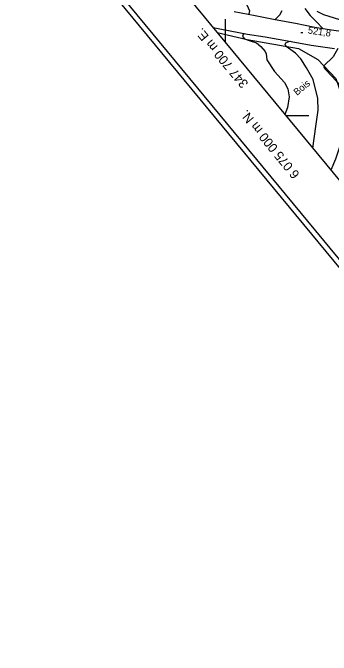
# Model space of a CAD drawing. Extents: x 347059 to 352153, y 6073752 to 6078601.
# Drawn here: x 347561.7 to 347769, y 6074648.1 to 6075066.9 of the extents above; entities that cross this region are included whole.
import ezdxf

# ---------------------------------------------------------------- set-up
doc = ezdxf.new("R2010")
doc.units = 0
for name, color, linetype in [('Level 1', 7, 'Continuous'), ('Level 19', 7, 'Continuous'), ('Level 2', 7, 'Continuous'), ('Level 21', 7, 'Continuous'), ('Level 3', 7, 'Continuous'), ('Level 44', 7, 'Continuous'), ('Level 60', 7, 'Continuous'), ('Level 61', 7, 'Continuous')]:
    doc.layers.add(name, color=color, linetype=linetype)

msp = doc.modelspace()

# ---------------------------------------------------------------- linework, layer by layer
at = {"layer": 'Level 1'}
msp.add_lwpolyline([(347773.33, 6075043.59), (347770.36, 6075038.18), (347764.36, 6075032.34), (347764.3, 6075031.5), (347765.2, 6075030.13), (347770, 6075025.24), (347773.43, 6075021.34), (347774.76, 6075019.13), (347775.23, 6075017), (347776.99, 6075008.78), (347777.41, 6075001.82), (347777.76, 6074999.99), (347778.25, 6074993.54), (347779.06, 6074993.15)], dxfattribs=at)
at = {"layer": 'Level 19'}
for points in [[(347732.67, 6075062.66), (347735.71, 6075065.67), (347737.22, 6075068.49)], [(347751.92, 6075069.68), (347755.45, 6075065.18), (347759.56, 6075061.15), (347763.54, 6075056.73)]]:
    msp.add_lwpolyline(points, dxfattribs=at)
at = {"layer": 'Level 2'}
for points in [[(347693.09, 6075107.08), (347696.94, 6075103.34), (347702.44, 6075093.04), (347704.43, 6075086.79), (347706.07, 6075083.88), (347708.88, 6075077.1), (347712.23, 6075074.08), (347714.07, 6075072.05), (347715.8, 6075068.14), (347715.35, 6075065.99)], [(347712.19, 6075053.53), (347711.63, 6075052.79), (347711.3, 6075051.45), (347712.63, 6075050.05), (347715.71, 6075048.92), (347720.4, 6075047.29), (347723.31, 6075044.95), (347726.06, 6075041.69), (347726.8, 6075040.19), (347727.11, 6075036.21)], [(347757.15, 6074978.58), (347759.13, 6074992.7), (347760.47, 6075003.39), (347760.32, 6075010.96), (347757.26, 6075023.39), (347753.07, 6075031.02), (347749.24, 6075036.97), (347745.8, 6075040.72), (347739.66, 6075045), (347739.14, 6075046.55), (347739.5, 6075047.39), (347740.68, 6075047.72)], [(347742.5, 6075048.39), (347742.31, 6075048.15), (347740.68, 6075047.72)], [(347727.11, 6075036.21), (347732.09, 6075028.59), (347738.57, 6075021.56), (347740.81, 6075017.34), (347741.67, 6075012.23), (347740.64, 6075005.28), (347738.95, 6075000.61)]]:
    msp.add_lwpolyline(points, dxfattribs=at)
at = {"layer": 'Level 21'}
for points in [[(347705.83, 6075067.75), (347719.45, 6075065.23), (347732.67, 6075062.66), (347745.79, 6075060.13), (347758.5, 6075057.48), (347763.54, 6075056.73), (347770.69, 6075055.65), (347782.01, 6075054.06), (347794.01, 6075052.37), (347806.38, 6075050.08), (347821.95, 6075047.53), (347837.03, 6075045.32), (347852.37, 6075043.16), (347871.71, 6075040.15), (347874.49, 6075042.05), (347876.01, 6075044), (347876.24, 6075047.77), (347876.48, 6075053.82), (347874.97, 6075059.22), (347871.12, 6075070.29)], [(347692.07, 6075057.34), (347697.53, 6075056.18), (347714.51, 6075053.11), (347726.02, 6075051.26), (347742.92, 6075048.32), (347756.03, 6075045.91), (347771.32, 6075043.76)]]:
    msp.add_lwpolyline(points, dxfattribs=at)
at = {"layer": 'Level 3'}
msp.add_line((347749.37, 6075054.19), (347750.56, 6075054.01), dxfattribs=at)
at = {"layer": 'Level 44'}
for points in [[(347861.15, 6075079.91), (347865.37, 6075057.26), (347869.96, 6075052.12), (347876.09, 6075046.92), (347875.58, 6075044.84), (347872.78, 6075041.91), (347817.9, 6075050.53), (347785.78, 6075058.96), (347764.27, 6075065.62), (347759.87, 6075067.81)], [(347694.84, 6075054), (347714.37, 6075049.54), (347747.86, 6075043.77), (347760.26, 6075036.39), (347771.98, 6075024.12), (347777.92, 6075007.16), (347780.53, 6074997.41), (347771.93, 6074971.61), (347768.87, 6074964.4)]]:
    msp.add_lwpolyline(points, dxfattribs=at)
at = {"layer": 'Level 60'}
for p, q in [((347700, 6075062.75), (347700, 6075047.75)), ((347739.47, 6075000), (347754.54, 6075000))]:
    msp.add_line(p, q, dxfattribs=at)
msp.add_lwpolyline([(347109.95, 6075761.81), (348728.53, 6073803.05), (351407.22, 6076016.53), (349788.63, 6077975.29)], close=True, dxfattribs=at)
for points in [[(347058.77, 6075766.69), (348723.67, 6073751.88)], [(347063.49, 6075766.23), (348724.12, 6073756.59)]]:
    msp.add_lwpolyline(points, dxfattribs=at)

# ---------------------------------------------------------------- texts
at = {"layer": 'Level 3'}
msp.add_text('521,8', height=4.5, rotation=351.7601, dxfattribs=at).set_placement((347753.64, 6075053.52))
at = {"layer": 'Level 44'}
msp.add_text('Bois', height=4.5, rotation=39.568, dxfattribs=at).set_placement((347746.79, 6075012.76))
at = {"layer": 'Level 61'}
for s, height, rotation, p in [('347 700 m E. ', 6.0001, 129.813, (347715.43, 6075020.94)), ('6 075 000 m N.', 6, 129.3644, (347748.82, 6074961.81))]:
    msp.add_text(s, height=height, rotation=rotation, dxfattribs=at).set_placement(p)

doc.saveas('drawing.dxf')
